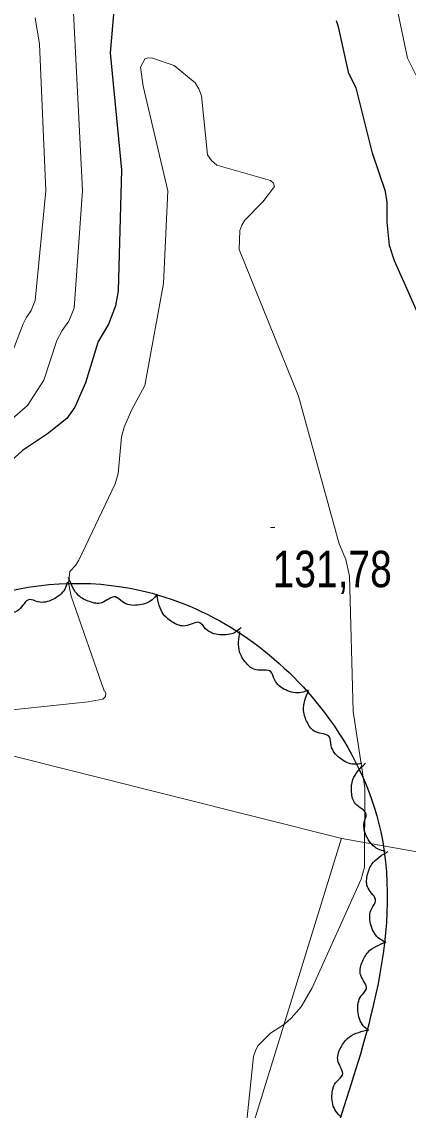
# Model space of a CAD drawing. Extents: x 483843 to 488449, y 4381269 to 4384483.
# Drawn here: x 486735.6 to 486828.4, y 4382813.6 to 4383075.2 of the extents above; entities that cross this region are included whole.
import ezdxf

# ---------------------------------------------------------------- set-up
doc = ezdxf.new("R2010")
doc.units = 0
doc.header["$LTSCALE"] = 3.8
for name, color, linetype, lineweight in [('27', 7, 'Continuous', 25), ('51', 7, 'Continuous', 13), ('7', 7, 'Continuous', 13), ('8', 7, 'Continuous', 25), ('9', 7, 'Continuous', 13)]:
    doc.layers.add(name, color=color, linetype=linetype, lineweight=lineweight)

msp = doc.modelspace()

# ---------------------------------------------------------------- linework, layer by layer
at = {"layer": '27'}
for points in [[(486510.56, 4382972.83), (486592.89, 4382960.7), (486601.82, 4382957.51), (486605.65, 4382949.21), (486605.01, 4382945.38), (486612.67, 4382941.55), (486617.14, 4382941.55), (486645.86, 4382947.29), (486666.92, 4382951.76), (486682.87, 4382958.79), (486691.17, 4382972.2), (486697.55, 4382995.18), (486698.19, 4383013.7), (486700.1, 4383028.38), (486705.21, 4383044.98), (486712.23, 4383062.86), (486713.51, 4383076.27), (486713.51, 4383089.04), (486710.95, 4383094.79), (486707.76, 4383100.53), (486695, 4383117.13), (486669.47, 4383126.71), (486659.9, 4383138.2), (486650.96, 4383150.33), (486637.56, 4383166.93), (486626.71, 4383177.15), (486626.71, 4383182.26), (486685.43, 4383205.88), (486717.33, 4383225.68), (486728.82, 4383230.78), (486732.65, 4383230.78), (486739.03, 4383228.87), (486743.5, 4383227.59), (486748.61, 4383221.21), (486745.41, 4383218.01), (486738.39, 4383203.97), (486732.65, 4383177.15), (486727.55, 4383157.36), (486725.63, 4383141.39), (486727.55, 4383133.73), (486765.2, 4383119.05), (486811.79, 4383105), (486813.06, 4383104.36), (486819.44, 4383106.92), (486824.55, 4383113.3), (486825.19, 4383127.35), (486820.08, 4383159.91), (486816.89, 4383173.96), (486816.89, 4383178.43), (486819.44, 4383183.54), (486826.46, 4383182.9), (486839.23, 4383173.96), (486851.35, 4383158.63), (486851.35, 4383155.44), (486854.55, 4383149.7), (486860.29, 4383146.5), (486874.33, 4383147.78), (486881.35, 4383147.78), (486885.18, 4383146.5), (486885.82, 4383140.12), (486878.16, 4383135.65), (486855.18, 4383117.77), (486850.08, 4383106.92), (486844.33, 4383092.87), (486846.25, 4383073.72), (486850.08, 4383059.67), (486853.27, 4383048.81), (486859.01, 4383039.24), (486866.03, 4383030.3), (486874.97, 4383020.08), (486875.61, 4383011.78), (486873.05, 4382997.74), (486873.05, 4382979.86), (486877.52, 4382957.51), (486880.71, 4382931.33), (486896.03, 4382901.96), (486916.45, 4382878.98), (486920.28, 4382878.34), (486934.96, 4382878.98), (486953.46, 4382889.19), (486954.74, 4382904.52), (486949.64, 4382917.29), (486943.25, 4382926.22), (486931.13, 4382935.16), (486926.66, 4382940.27), (486927.94, 4382947.29), (486935.6, 4382954.32), (486935.6, 4382959.43), (486931.77, 4382975.39), (486917.73, 4383017.53), (486919, 4383028.38)], [(486286.37, 4382818.73), (486339.99, 4382829.8), (486391.37, 4382851.5), (486440.09, 4382863.84), (486483.65, 4382864.6), (486530.94, 4382876.91), (486556.13, 4382891.91), (486581.09, 4382903.76), (486654.31, 4382924.49), (486662.47, 4382925.04), (486711.17, 4382931.08), (486727.4, 4382937.04), (486766.91, 4382937.87), (486808.31, 4382909.18), (486821.81, 4382880.51), (486820.67, 4382841.64), (486812.49, 4382812.89), (486799.42, 4382770.69), (486791.78, 4382745.03), (486785, 4382714.29), (486784.58, 4382691.25), (486792.33, 4382675.66), (486812.73, 4382668.89), (486834.8, 4382649.92), (486842.09, 4382627.43), (486847.24, 4382607.13), (486841.07, 4382582.93), (486840.3, 4382544.36), (486820.33, 4382480.87), (486817.63, 4382459.06), (486815.97, 4382420.47), (486812.52, 4382387.85), (486799.99, 4382362.84), (486771.04, 4382337.85), (486733.51, 4382314.2), (486712.72, 4382296.59), (486687.38, 4382263.88), (486690.96, 4382229.15), (486713.22, 4382200.82), (486764.33, 4382192.43), (486778.5, 4382149.68), (486779.01, 4382117.89), (486787.15, 4382072.98), (486813.93, 4382065.66), (486857.54, 4382071.08), (486866.35, 4382080.34), (486893.23, 4382096.95), (486915.85, 4382116.25), (486928.06, 4382127.9), (486936.43, 4382157.7), (486928.1, 4382176.05), (486914.22, 4382205.24), (486902.98, 4382218.81), (486885.61, 4382249.79), (486879.29, 4382279.36), (486884.99, 4382315.26), (486888.52, 4382343.76), (486907.35, 4382375.88), (486922.54, 4382388.35), (486945.58, 4382366.33), (486954.28, 4382323.31), (486963.51, 4382283.6), (486982.52, 4382253.24), (487009.26, 4382225.98), (487037.6, 4382230.32), (487058.96, 4382252.37), (487069.68, 4382284.84), (487065.95, 4382338.17), (487054.24, 4382363.72), (487038.01, 4382386.56), (487027.59, 4382400.37), (487012.06, 4382422.24), (486991.9, 4382450.1), (486977.88, 4382471.56), (486976.21, 4382486.9), (486980.43, 4382521.64), (487024.88, 4382562.69), (487055.81, 4382565.06), (487106.74, 4382596.8), (487155.96, 4382614.11), (487207.74, 4382666.72), (487232.21, 4382676.6), (487267.31, 4382683.94), (487282.71, 4382693.48), (487294.56, 4382707.98), (487340.16, 4382736.84), (487389.67, 4382736.07), (487421.36, 4382716.33), (487454.29, 4382680.57), (487455.44, 4382629.06), (487501.37, 4382598.97)], [(486746.5, 4382940.54), (486745.89, 4382938.88), (486743.04, 4382936.38), (486739.39, 4382935.82), (486737.4, 4382936.34), (486734.85, 4382933.87), (486731.98, 4382933.04), (486728.99, 4382933.49), (486725.16, 4382936.64)], [(486768.09, 4382937.65), (486766.92, 4382936.31), (486763.36, 4382935), (486759.75, 4382935.79), (486758.09, 4382936.99), (486754.81, 4382935.6), (486751.84, 4382935.85), (486749.21, 4382937.34), (486746.76, 4382941.65)], [(486788.28, 4382929.64), (486786.89, 4382928.53), (486783.15, 4382927.89), (486779.74, 4382929.32), (486778.32, 4382930.8), (486774.85, 4382930.03), (486771.97, 4382930.82), (486769.65, 4382932.76), (486768.03, 4382937.45)], [(486804.41, 4382914.56), (486802.73, 4382913.98), (486798.99, 4382914.64), (486796.27, 4382917.12), (486795.42, 4382918.99), (486791.89, 4382919.43), (486789.44, 4382921.13), (486787.91, 4382923.74), (486787.95, 4382928.7)], [(486817.24, 4382896.94), (486815.47, 4382896.77), (486811.98, 4382898.26), (486809.9, 4382901.3), (486809.5, 4382903.32), (486806.17, 4382904.55), (486804.18, 4382906.77), (486803.28, 4382909.66), (486804.46, 4382914.48)], [(486822.85, 4382875.86), (486821.16, 4382876.4), (486818.55, 4382879.16), (486817.86, 4382882.79), (486818.3, 4382884.79), (486815.74, 4382887.25), (486814.8, 4382890.09), (486815.13, 4382893.09), (486818.14, 4382897.04)], [(486822.67, 4382854.12), (486821.18, 4382855.08), (486819.38, 4382858.42), (486819.65, 4382862.1), (486820.59, 4382863.92), (486818.75, 4382866.97), (486818.58, 4382869.95), (486819.68, 4382872.76), (486823.6, 4382875.8)], [(486818.93, 4382832.77), (486817.6, 4382833.95), (486816.32, 4382837.52), (486817.14, 4382841.12), (486818.36, 4382842.78), (486816.99, 4382846.06), (486817.27, 4382849.04), (486818.79, 4382851.65), (486823.12, 4382854.06)], [(486812.25, 4382812.08), (486811.04, 4382813.37), (486810.09, 4382817.05), (486811.24, 4382820.56), (486812.6, 4382822.1), (486811.54, 4382825.49), (486812.09, 4382828.43), (486813.84, 4382830.89), (486818.38, 4382832.9)]]:
    msp.add_spline(points, degree=3, dxfattribs=at)
at = {"layer": '51'}
for points in [[(486669.72, 4382914.77), (486812.46, 4382878.97), (486872.99, 4382868.23), (486875.9, 4382865.44), (486849.95, 4383012.66)], [(486636.2, 4382724.98), (486766.24, 4382729.42), (486812.41, 4382878.99)]]:
    msp.add_lwpolyline(points, dxfattribs=at)
at = {"layer": '7'}
msp.add_line((486795.33, 4382953.7), (486796.33, 4382953.7), dxfattribs=at)
at = {"layer": '8'}
for points in [[(486757.64, 4383077.9), (486756.78, 4383067.72), (486759.53, 4383039.62), (486758.71, 4383010.58), (486758.05, 4383006.95), (486756.39, 4383002.51), (486753.86, 4382998.21), (486753.79, 4382997.91), (486753.58, 4382997.35), (486750.9, 4382988.46), (486748.33, 4382982.57), (486746.35, 4382979.9), (486741.78, 4382976.16), (486735.77, 4382972.16), (486731.07, 4382967.96)], [(486832.96, 4383000.13), (486825.09, 4383017.74), (486823.92, 4383021.41), (486823.37, 4383027.02), (486823.37, 4383031.86), (486822.98, 4383034.44), (486819.82, 4383043.65), (486815.88, 4383059.3), (486814.11, 4383062.8), (486811.66, 4383074), (486811.19, 4383075.42)]]:
    msp.add_lwpolyline(points, dxfattribs=at)
at = {"layer": '9'}
for points in [[(486822.78, 4383092.5), (486828.25, 4383066.45), (486830.27, 4383062.44)], [(486556.59, 4382938.94), (486641.9, 4382944.92), (486653.23, 4382947.24), (486667.51, 4382952.2), (486680.17, 4382958.36), (486687.68, 4382960.82), (486688.37, 4382961.24), (486689, 4382961.72), (486692.95, 4382966.31), (486693.73, 4382966.81), (486694.6, 4382967.25), (486703.92, 4382969.98), (486716.62, 4382976.51), (486724.74, 4382981.92), (486727.79, 4382984.62), (486730.65, 4382988.96), (486735.87, 4383002.58), (486736.63, 4383004.02), (486737.84, 4383005.81), (486738.78, 4383008.22), (486741.36, 4383034.57), (486739.79, 4383069.85), (486738.78, 4383076.18)], [(486732.67, 4382979.27), (486736.9, 4382983.02), (486740.88, 4382989.06), (486744.01, 4382998.65), (486745.26, 4383001.04), (486746.89, 4383003.24), (486748.13, 4383006.41), (486750.12, 4383034.67), (486747.98, 4383077.38)], [(486789.16, 4383027.54), (486793.46, 4383031.97), (486796.25, 4383035.65), (486796.02, 4383036.41), (486795.36, 4383037.06), (486782.39, 4383040.71), (486781.15, 4383041.85), (486780.2, 4383043.22), (486778.73, 4383057.4), (486778.08, 4383059.07), (486777.2, 4383060.57), (486772.16, 4383064.68), (486766.97, 4383066.5), (486766, 4383066.56), (486765.22, 4383066.42), (486764.09, 4383064.33), (486764.71, 4383059.73), (486770.62, 4383034.55), (486769.65, 4383012.34), (486765.14, 4382987.8), (486761.9, 4382981.85), (486760.13, 4382977.79), (486759.53, 4382975.45), (486758.69, 4382966.63), (486758, 4382964.17), (486749.29, 4382945.83), (486748.5, 4382944.53), (486747.1, 4382943.12), (486746.75, 4382940.36), (486747.44, 4382937.15), (486755.38, 4382914.45), (486755.52, 4382914.34), (486755.6, 4382914.19), (486755.74, 4382913.75), (486755.71, 4382913.22), (486755.64, 4382913.07), (486755.55, 4382912.93), (486755.01, 4382912.45), (486751.48, 4382911.76), (486721.83, 4382908.68)], [(486788.7, 4382801.94), (486791.21, 4382826.53), (486791.69, 4382827.89), (486792.28, 4382829.09), (486795.29, 4382832.13), (486798.68, 4382834.34), (486800.29, 4382835.72), (486802.69, 4382838.47), (486805.35, 4382843.03), (486817.07, 4382869.14), (486817.88, 4382872.08), (486817.96, 4382891.11), (486815.21, 4382909.49), (486814.31, 4382942.01), (486813.43, 4382946.02), (486811.86, 4382949.74), (486802.03, 4382985.26), (486787.8, 4383020.5), (486787.94, 4383025.05), (486788.45, 4383026.3), (486789.16, 4383027.54)]]:
    msp.add_lwpolyline(points, dxfattribs=at)

# ---------------------------------------------------------------- texts
at = {"layer": '7', "width": 0.8}
msp.add_text('131,78', height=8.75, dxfattribs=at).set_placement((486795.83, 4382939.33))

doc.saveas('drawing.dxf')
